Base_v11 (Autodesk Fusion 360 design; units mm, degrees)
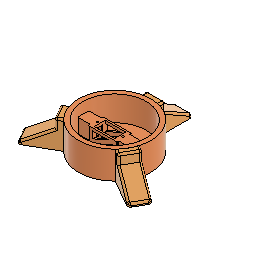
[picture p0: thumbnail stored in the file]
parameter "d22" = 2.3
parameter "d91" = 2.35
parameter "d96" = 8
sketch "Sketch1" plane through (0, 0, 0) normal (0, 0, 1) x axis (1, 0, 0)
  line L1 (6.1, 5.9) -> (6.1, -5.9)
  line L2 (-5.15, 6.1) -> (-5.15, -6.4)
  line L3 (6.1, 6) -> (-16.4, 6)
  line L4 (6.1, -6.3) -> (6.1, 6)
  line L5 (-16.4, -6.3) -> (6.1, -6.3)
  line L6 (-16.4, 6) -> (-16.4, -6.3)
  line L7 (6.1, -6.3) -> (-16.4, 6)
  line L8 (-16.4, -6.3) -> (6.1, 6)
  line L9 (6.25, 6) -> (-16.55, 6)
  line L10 (6.25, -6.3) -> (6.25, 6)
  line L11 (-16.55, -6.3) -> (6.25, -6.3)
  line L12 (-16.55, 6) -> (-16.55, -6.3)
  line L13 (6.25, -6.3) -> (-16.55, 6)
  line L14 (-16.55, -6.3) -> (6.25, 6)
  line L15 (10.9, 6) -> (-21.2, 6)
  line L16 (10.9, -6.3) -> (10.9, 6)
  line L17 (-21.2, -6.3) -> (10.9, -6.3)
  line L18 (-21.2, 6) -> (-21.2, -6.3)
  line L19 (10.9, -6.3) -> (-21.2, 6)
  line L20 (-21.2, -6.3) -> (10.9, 6)
  line L21 (-34.9997, -0.15) -> (34.9997, -0.15)
  line L22 (-21.2, 8) -> (10.9, 8)
  line L23 (-21.2, -8.3) -> (-21.2, 8)
  line L24 (10.9, -8.3) -> (-21.2, -8.3)
  line L25 (10.9, 8) -> (10.9, -8.3)
  line L26 (-21.2, -8.3) -> (10.9, 8)
  line L27 (10.9, -8.3) -> (-21.2, 8)
  line L28 (-34.4819, 6) -> (34.4819, 6)
  line L29 (-34.4283, -6.3) -> (34.4283, -6.3)
  circle C1 centre (0, 0) radius 40
  circle C2 centre (0, 0) radius 35
  circle C3 centre (0.1, 0) radius 6
  circle C4 centre (8.75, 0) radius 1.1
  circle C5 centre (-19.05, 0) radius 1.1
  point P1 (0, 0)
  point P2 (0, 0)
  point P3 (0, 0)
  point P15 (-5.15, -0.15)
  point P20 (-5.15, -0.15)
  point P25 (-5.15, -0.15)
  point P26 (34.9997, -0.15)
  point P27 (-34.9997, -0.15)
  point P32 (-5.15, -0.15)
  point P33 (34.4283, -6.3)
  point P34 (34.4819, 6)
  point P35 (-34.4283, -6.3)
  point P36 (-34.4819, 6)
  point P13 (6.1, -6.3)
  point P14 (-16.4, -6.3)
  point P12 (6.1, 6)
  point P18 (6.25, -6.3)
  point P19 (-16.55, -6.3)
  point P17 (6.25, 6)
  point P23 (10.9, -6.3)
  point P24 (-21.2, -6.3)
  point P22 (10.9, 6)
  point P30 (-21.2, -8.3)
  point P31 (10.9, -8.3)
  point P29 (-21.2, 8)
  point P5 (8.75, 0)
  point P6 (-19.05, 0)
  point P9 (-5.15, -6.4)
  point P10 (-5.15, 6.1)
  coincident P1 P2
  coincident P1 P3
  tangent C3 L1
  horizontal L3
  perpendicular L3 L4
  parallel L3 L5
  parallel L4 L6
  coincident L7 P15
  coincident L8 P15
  midpoint L2 P15
  horizontal L9
  perpendicular L9 L10
  parallel L9 L11
  parallel L10 L12
  coincident L13 P20
  coincident L14 P20
  coincident P15 P20
  horizontal L15
  perpendicular L15 L16
  parallel L15 L17
  parallel L16 L18
  coincident L19 P25
  coincident L20 P25
  coincident P15 P25
  coincident C2 P26
  coincident C2 P27
  horizontal L21
  horizontal L22
  perpendicular L22 L23
  parallel L22 L24
  parallel L23 L25
  coincident L26 P32
  coincident L27 P32
  coincident P25 P32
  symmetric L9 L11 L21
  perpendicular L2 L15
  perpendicular L6 L28
  horizontal L29
  coincident C2 P33
  coincident C2 P34
  coincident C2 P35
  coincident C2 P36
  dimension "d3" diameter C1 = 80
  dimension "d4" diameter C2 = 70
  dimension "d13" diameter C3 = 12
  dimension "d21" diameter C4 = 2.2
  dimension "d23" diameter C5 = 2.2 (= "d21")
  dimension "d84" distance L1 L2 = 11.25 (= "( 22.5 / 2 ) * 1 mm")
  dimension "d85" distance P13 P14 = 22.5
  dimension "d86" distance P12 P13 = 12.3
  dimension "d87" distance P18 P19 = 22.8
  dimension "d88" distance P17 P18 = 12.3 (= "d86")
  dimension "d89" distance P23 P24 = 32.1
  dimension "d90" distance P22 P23 = 12.3 (= "d86")
  dimension "d98" distance P30 P31 = 32.1 (= "d89")
  dimension "d99" distance P29 P30 = 16.3 (= "d86 + 4 mm")
  dimension "d108" distance P5 L4 = 2.65 (= "1.55 mm + 1.1 mm")
  dimension "d109" distance P6 L6 = 2.65 (= "d108")
  dimension "d110" distance P9 P10 = 12.5
  dimension "d111" distance L21 L29 = 6.15 (= "d86 / 2")
  dimension "d112" distance L21 L28 = 6.15 (= "d86 / 2")
extrude "Extrude1" new body sketch "Sketch1" profile of C1 C2 along normal blind 30.7 (= "22.7 mm + 3 mm + 4 mm + 1 mm")
sketch "Sketch3" plane through (0, 0, 0) normal (0, 0, -1) x axis (1, 0, 0)
  line L1 (40, 0) -> (-40, 0)
  line L2 (4.6764, -3) -> (4.6764, 0)
  line L3 (12.6764, -3) -> (4.6764, -3)
  line L4 (12.6764, 3) -> (12.6764, -3)
  line L5 (4.6764, 3) -> (12.6764, 3)
  line L6 (4.6764, -3) -> (4.6764, 3)
  line L7 (-14.7236, 3) -> (-14.7236, 0)
  line L8 (-22.7236, 3) -> (-14.7236, 3)
  line L9 (-22.7236, -3) -> (-22.7236, 3)
  line L10 (-14.7236, -3) -> (-22.7236, -3)
  line L11 (-14.7236, 3) -> (-14.7236, -3)
  circle C1 centre (0, 0) radius 40
  circle C2 centre (0, 0) radius 36.5
  circle C3 centre (0, 0) radius 35
  point P3 (-40, 0)
  point P4 (40, 0)
  point P1 (0, 0)
  point P5 (0, 0)
  point P6 (4.6764, 0)
  point P11 (-14.7236, 0)
  point P7 (4.6764, -3)
  point P10 (4.6764, 3)
  point P8 (12.6764, -3)
  point P12 (-14.7236, 3)
  point P15 (-14.7236, -3)
  point P14 (-22.7236, -3)
  coincident C1 P3
  coincident C1 P4
  horizontal L1
  coincident P1 P5
  coincident L1 P6
  perpendicular L1 L2
  horizontal L3
  vertical L4
  horizontal L5
  vertical L6
  coincident L1 P11
  perpendicular L1 L7
  horizontal L8
  vertical L9
  horizontal L10
  vertical L11
  dimension "d45" diameter C2 = 73
  dimension "d46" distance P6 P7 = 3
  dimension "d47" distance P7 P10 = 6
  dimension "d48" distance P7 P8 = 8
  dimension "d50" distance P11 P12 = 3
  dimension "d52" distance P12 P15 = 6
  dimension "d70" distance P14 P15 = 8
component_insert "Component Insert4"
sketch "Sketch4" plane through (0, 0, 30.7) normal (0, 0, 1) x axis (-1, 0, 0)
  line L1 (0, 0) -> (0, -40)
  line L2 (-34.641, 20) -> (0, 0)
  line L3 (40, 0.0182) -> (-40, 0.0182)
  line L4 (34.641, 20) -> (0, 0)
  circle C1 centre (0, 0) radius 35
  circle C2 centre (0, 0) radius 40
  circle C3 centre (0, 0) radius 40
  point P4 (0, -40)
  point P1 (0, 0)
  point P5 (0, 0)
  point P6 (0, 0)
  point P7 (-34.641, 20)
  point P8 (-40, 0.0182)
  point P9 (40, 0.0182)
  point P2 (0, 0)
  point P10 (0, 0)
  point P11 (34.641, 20)
  concentric C1 C3
  coincident C2 P4
  coincident P1 P5
  coincident P1 P6
  coincident C3 P7
  coincident C3 P8
  coincident C3 P9
  horizontal L3
  perpendicular L1 L3
  coincident P2 P10
  coincident C3 P11
  dimension "d55" diameter C3 = 80
  dimension "d56" angle L1 L2 = 120 (= "( 360 / 3 ) * 1 deg")
  dimension "d57" angle L1 L4 = 120 (= "( 360 / 3 ) * 1 deg")
joint "Assemble" alignAngle 30 alignOffsetX 0 alignOffsetY 0 alignOffsetZ -30.7
component_insert "Component Insert5"
joint "Assemble" alignAngle -90 alignOffsetX 0 alignOffsetY 0 alignOffsetZ -30.7
component_insert "Component Insert6"
joint "Assemble" alignAngle 150 alignOffsetX 0 alignOffsetY 0 alignOffsetZ -30.7
sketch "Sketch2" plane through (0, 0, 0) normal (0, 0, -1) x axis (1, 0, 0)
  circle C1 centre (8.6764, 0) radius 3.5
  circle C2 centre (-18.7236, 0) radius 3.5
  circle C3 centre (0, 0) radius 40
  circle C4 centre (0, 0) radius 35
  dimension "d33" diameter C1 = 7
  dimension "d34" diameter C2 = 7
extrude "Extrude9" add sketch "Sketch1" profile of C2 L9 L10 L11 L12 L15 L17 L22 L23 L24 L25 along normal blind 3
extrude "Extrude10" add sketch "Sketch1" profile of C2 C4 C5 L9 L10 L11 L12 L15 L16 L17 L18 L22 L23 L24 L25 L28 L29 along normal blind 18.9 (= "15.9 mm + 3 mm")
sketch "Sketch9" plane through (-16.55, 0, 0) normal (1, 0, 0) x axis (0, 1, 0)
  line L1 (6, 3) -> (-6.3, 3)
  line L2 (6, 18.9) -> (6, 3)
  line L3 (-6.3, 18.9) -> (6, 18.9)
  line L4 (-6.3, 3) -> (-6.3, 18.9)
  line L5 (3, 15.9) -> (-3.3, 15.9)
  line L6 (3, 0) -> (3, 15.9)
  line L7 (-3.3, 0) -> (3, 0)
  line L8 (-3.3, 15.9) -> (-3.3, 0)
  point P6 (-3.3, 15.9)
  point P7 (3, 15.9)
  point P9 (-3.3, 0)
  horizontal L5
  vertical L6
  horizontal L7
  vertical L8
  dimension "d127" distance P6 P7 = 6.3 (= "12.3 mm - 6 mm")
  dimension "d128" distance P6 P9 = 15.9
  dimension "d129" distance L3 L5 = 3
  dimension "d130" distance L4 L8 = 3
extrude "Extrude13" cut sketch "Sketch9" profile of L1 L5 L6 L8 against normal blind 23.45
sketch "Sketch8" plane through (0, 0, 0) normal (0, 0, -1) x axis (1, 0, 0)
  circle C1 centre (8.75, 0) radius 1.1
  circle C2 centre (-19.05, 0) radius 1.1
  circle C3 centre (0, 0) radius 40
  circle C4 centre (-19.05, 0) radius 3.5
  circle C5 centre (8.75, 0) radius 3.5
  concentric C2 C4
  concentric C1 C5
  dimension "d123" diameter C4 = 7
  dimension "d124" diameter C5 = 7
extrude "Extrude12" cut sketch "Sketch8" profile of C1 C2 C4 C5 against normal blind 15.9
sketch "Sketch10" plane through (0, -8.3, 0) normal (0, -1, 0) x axis (1, 0, 0)
  line L1 (10.9, 3) -> (-21.2, 3)
  line L2 (10.9, 18.9) -> (10.9, 3)
  line L3 (-21.2, 18.9) -> (10.9, 18.9)
  line L4 (-21.2, 3) -> (-21.2, 18.9)
sketch "Sketch11" plane through (0, -8.3, 0) normal (0, -1, 0) x axis (1, 0, 0)
  line L1 (-5.15, 3) -> (-5.15, 18.9)
  line L2 (-16.55, 15.9) -> (6.25, 15.9)
  line L3 (-16.55, 6) -> (-16.55, 15.9)
  line L4 (6.25, 6) -> (-16.55, 6)
  line L5 (6.25, 15.9) -> (6.25, 6)
  line L6 (-16.55, 6) -> (6.25, 15.9)
  line L7 (6.25, 6) -> (-16.55, 15.9)
  line L8 (1.2285, 15.9) -> (-16.55, 8.1804)
  line L9 (6.25, 13.7196) -> (-11.5285, 6)
  point P8 (-5.15, 10.95)
  point P9 (-16.55, 8.1804)
  point P10 (1.2285, 15.9)
  point P11 (6.25, 13.7196)
  point P12 (-11.5285, 6)
  point P2 (-5.15, 18.9)
  point P3 (-5.15, 3)
  point P6 (-16.55, 6)
  point P7 (6.25, 6)
  point P5 (-16.55, 15.9)
  horizontal L2
  perpendicular L2 L3
  parallel L2 L4
  parallel L3 L5
  coincident L6 P8
  coincident L7 P8
  midpoint L1 P8
  parallel L6 L8
  parallel L6 L9
  coincident L3 P9
  coincident L2 P10
  coincident L5 P11
  coincident L4 P12
  dimension "d142" distance P2 P3 = 15.9
  dimension "d143" distance P6 P7 = 22.8 (= "d87")
  dimension "d144" distance P5 P6 = 9.9 (= "15.9 mm - 6 mm")
  dimension "d145" distance L6 L8 = 2
  dimension "d146" distance L6 L9 = 2
extrude "Extrude15" cut sketch "Sketch11" profile of L2 L3 L4 L5 L8 L9 against normal blind 3
mirror "Mirror1" mirrorStitchTolerance 0.1
fillet "Fillet1" radius 1
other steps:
joint_origin "JointOrigin4"
joint_origin "JointOrigin5"
joint_origin "JointOrigin6"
